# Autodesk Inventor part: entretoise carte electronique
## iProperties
Author: Administrateur
Created: 2001-04
Part Number: entretoise carte electronique
Material: Par défaut
Document SubType Name: Modélisation
Designer: Administrateur
Control State: 0
Master: False
Checked Out: False
PropertySet Name: Design Tracking Control
Shininess: 20.0
PropertySet Name: _Private Model Information
Length Units: 11269
Angle Units: 11283
Time Units: 11279
Mass Units: 11290
Length Display Precision: 3
Angle Display Precision: 2
Compacted: False
Density: 0.0
Volumn: 0.0
Area: 0.0
PropertySet Name: Model Information
